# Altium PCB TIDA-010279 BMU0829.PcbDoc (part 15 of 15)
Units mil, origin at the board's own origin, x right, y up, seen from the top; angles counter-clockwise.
Board outline 11269.69 x 4438.98 mil, 4 copper layers (Top Layer, Signal Layer 1, Signal Layer 2, Bottom Layer), stack 61.6 mil thick; 1494 components, 725 nets, 3766 pads, 2728 vias.
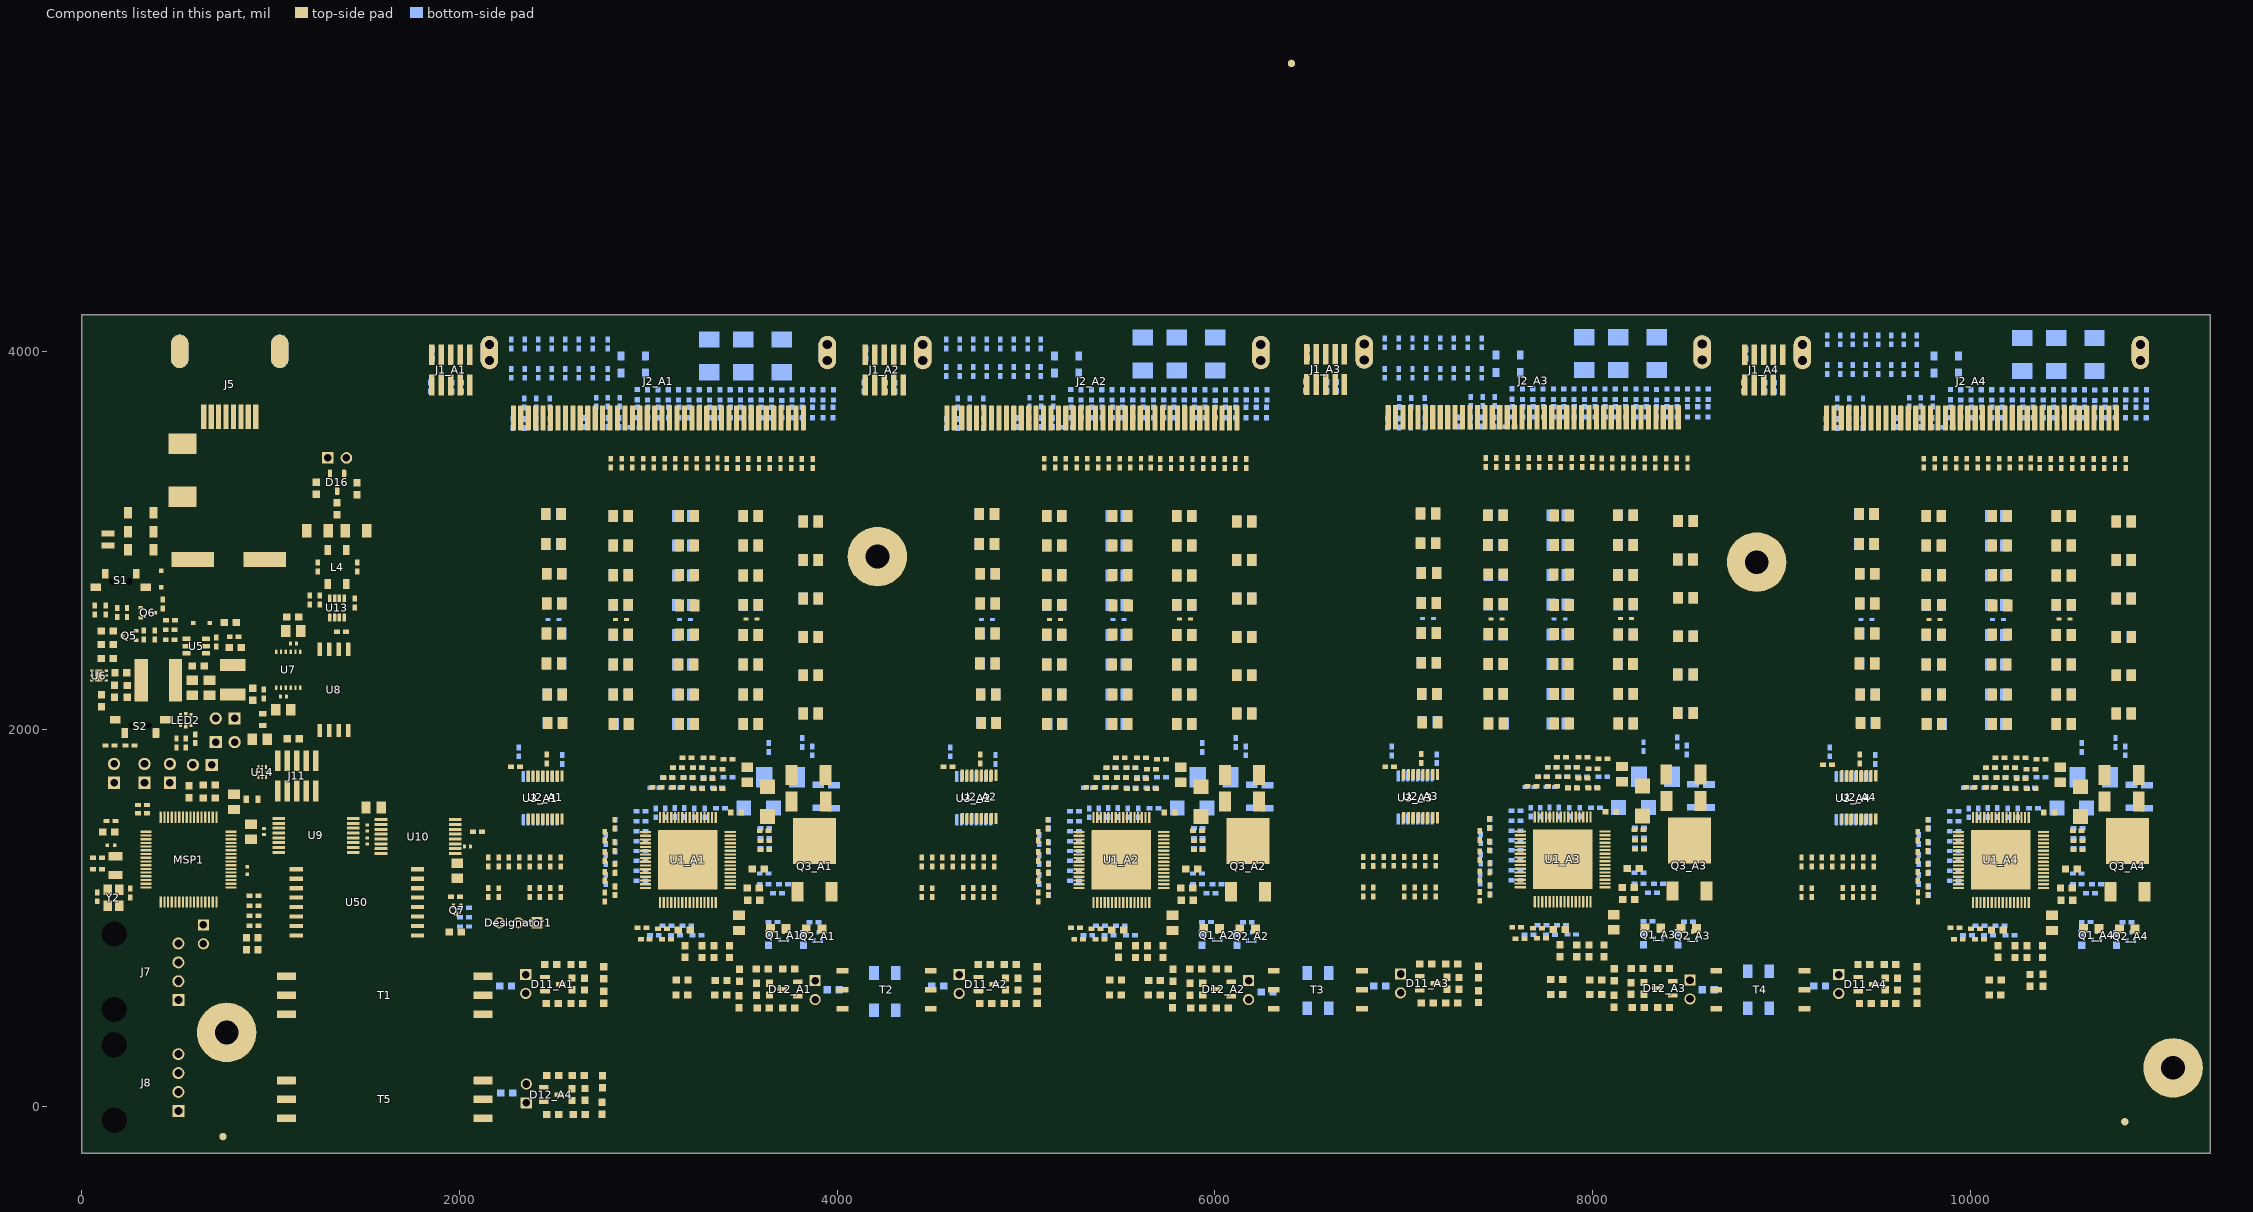
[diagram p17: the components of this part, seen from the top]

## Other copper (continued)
Bottom Layer:
  rectangle net DDGND: 1262.32,2387.93 1446.1,3280.04
  region net DDGND: 1272.87,2390.64 1272.87,2675.78 972.31,2675.78 972.31,2390.64
  pour cut-out: 1850.39,833.54 2280.32,833.54 2280.32,423.23 1850.39,423.23
  region net PGND: 1072.83,2234.25 1220.47,2234.25 1220.47,2155.51 1072.83,2155.51
  region net GND_Stage2: 1948.82,1574.8 2066.93,1574.8 2076.77,1564.96 2076.77,1427.17 2057.09,1407.48 1948.82,1407.48
  region net PGND: 875.98,1456.69 1023.62,1456.69 1023.62,1259.84 875.98,1259.84
  region net CELL0_A1: 2495.94,1980.81 2371.07,1980.81 2371.07,2251.95 2495.94,2251.95
  region net CB0_A1: 2638.57,1980.81 2510.32,1980.81 2510.32,2251.95 2638.57,2251.95
  region net CELL4_A1: 2721.94,2242.76 2846.81,2242.76 2846.81,1971.62 2721.94,1971.62
  region net CB4_A1: 2860.81,2242.76 2985.68,2242.76 2985.68,1971.62 2860.81,1971.62
  region net CELL8_A1: 3063.13,2242.76 3188.01,2242.76 3188.01,1971.62 3063.13,1971.62
  region net CB8_A1: 3200.11,2242.76 3324.99,2242.76 3324.99,1971.62 3200.11,1971.62
  region net CELL12_A1: 3417.1,2242.76 3541.98,2242.76 3541.98,1971.62 3417.1,1971.62
  region net CB12_A1: 3554.09,2242.76 3678.96,2242.76 3678.96,1971.62 3554.09,1971.62
  pour cut-out: 3933.27,791.2 4063.31,792.06 4063.31,419.92 4061.34,417.95 3933.27,417.95
  pour cut-out: 4145.41,833.54 4575.34,833.54 4575.34,423.23 4145.41,423.23
  region net ModuleP_L_A1: 3740.16,1604.33 4055.12,1604.33 4055.12,1250 3740.16,1250
  region net CELL16_A1: 3768.85,2361.15 3856.86,2361.15 3856.86,1979.4 3768.85,1979.4
  region net CB16_A1: 3867.28,2358.65 3955.3,2358.65 3955.3,1979.4 3867.28,1979.4
  region net CELL0_A2: 4790.96,1980.81 4666.08,1980.81 4666.08,2251.95 4790.96,2251.95
  region net CB0_A2: 4933.59,1980.81 4805.33,1980.81 4805.33,2251.95 4933.59,2251.95
  region net CELL4_A2: 5016.95,2242.76 5141.83,2242.76 5141.83,1971.62 5016.95,1971.62
  region net CB4_A2: 5155.82,2242.76 5280.7,2242.76 5280.7,1971.62 5155.82,1971.62
  region net CELL8_A2: 5358.15,2242.76 5483.02,2242.76 5483.02,1971.62 5358.15,1971.62
  region net CB8_A2: 5495.13,2242.76 5620.01,2242.76 5620.01,1971.62 5495.13,1971.62
  region net CELL1_A1: 2370.64,2560.13 2495.51,2560.13 2495.51,2288.99 2370.64,2288.99
  region net CB1_A1: 2509.88,2560.13 2636.22,2560.13 2636.22,2288.99 2509.88,2288.99
  region net CELL2_A1: 2370.64,2877.5 2495.51,2877.5 2495.51,2606.36 2370.64,2606.36
  region net CB2_A1: 2509.88,2877.5 2636.22,2877.5 2636.22,2606.36 2509.88,2606.36
  region net CELL5_A1: 2721.94,2560.13 2846.81,2560.13 2846.81,2288.99 2721.94,2288.99
  region net CB5_A1: 2860.81,2560.13 2985.68,2560.13 2985.68,2288.99 2860.81,2288.99
  region net CELL6_A1: 2721.94,2877.5 2846.81,2877.5 2846.81,2606.36 2721.94,2606.36
  region net CB6_A1: 2860.81,2877.5 2985.68,2877.5 2985.68,2606.36 2860.81,2606.36
  region net CELL3_A1: 2495.94,2927.18 2371.07,2927.18 2371.07,3198.32 2495.94,3198.32
  region net CB3_A1: 2638.57,2927.18 2510.32,2927.18 2510.32,3198.32 2638.57,3198.32
  region net CELL7_A1: 2721.94,3194.87 2846.81,3194.87 2846.81,2923.73 2721.94,2923.73
  region net CB7_A1: 2860.81,3194.87 2985.68,3194.87 2985.68,2923.73 2860.81,2923.73
  region net CELL9_A1: 3063.13,2560.13 3188.01,2560.13 3188.01,2288.99 3063.13,2288.99
  region net CB9_A1: 3200.11,2560.13 3324.99,2560.13 3324.99,2288.99 3200.11,2288.99
  region net CELL10_A1: 3063.13,2877.5 3188.01,2877.5 3188.01,2606.36 3063.13,2606.36
  pour cut-out: 4072.93,3779.53 4072.93,1197.01 3538.36,1197.01 3538.36,1491.73 3033.85,1491.73 3033.85,1134.49 2932.47,1136.13 2861.84,1065.51 2684.74,1065.51 2684.74,3336.63 2803.93,3336.63 2859.17,3391.88 2859.17,3508.39 2972.64,3508.39 3009.17,3544.92 3009.17,3779.53
  region net CELL13_A1: 3417.1,2560.13 3541.98,2560.13 3541.98,2288.99 3417.1,2288.99
  region net CB10_A1: 3200.11,2877.5 3324.99,2877.5 3324.99,2606.36 3200.11,2606.36
  region net CELL14_A1: 3417.1,2877.5 3541.98,2877.5 3541.98,2606.36 3417.1,2606.36
  region net CELL11_A1: 3072.49,3195.54 3188.01,3195.54 3188.01,2924.4 3072.49,2924.4
  region net CB11_A1: 3200.11,3194.87 3324.99,3194.87 3324.99,2923.73 3200.11,2923.73
  region net CELL15_A1: 3417.1,3195.54 3541.98,3195.54 3541.98,2924.4 3417.1,2924.4
  region net CELL17_A1: 3307.09,4055.12 3366.14,4055.12 3366.14,3986.22 3307.09,3986.22
  pour cut-out: 3097.29,4258.71 3097.29,3937.01 3896.33,3937.01 3896.33,4258.71
  region net CELL18_A1: 3494.09,4084.65 3543.31,4084.65 3553.15,4074.8 3553.15,3986.22 3494.09,3986.22
  region net CB13_A1: 3554.09,2560.13 3678.96,2560.13 3678.96,2288.99 3554.09,2288.99
  region net CB14_A1: 3554.09,2877.5 3678.96,2877.5 3678.96,2606.36 3554.09,2606.36
  region net CELL17_A1: 3768.53,2779.69 3856.54,2779.69 3856.54,2397.94 3768.53,2397.94
  region net CB17_A1: 3866.96,2777.19 3954.98,2777.19 3954.98,2397.94 3866.96,2397.94
  region net CELL1_A2: 4665.65,2560.13 4790.53,2560.13 4790.53,2288.99 4665.65,2288.99
  region net CB1_A2: 4804.9,2560.13 4931.23,2560.13 4931.23,2288.99 4804.9,2288.99
  region net CELL2_A2: 4665.65,2877.5 4790.53,2877.5 4790.53,2606.36 4665.65,2606.36
  region net CB2_A2: 4804.9,2877.5 4931.23,2877.5 4931.23,2606.36 4804.9,2606.36
  region net CB18_A1: 3866.1,3195.73 3954.11,3195.73 3954.11,2816.48 3866.1,2816.48
  region net CB15_A1: 3554.09,3194.87 3678.96,3194.87 3678.96,2923.73 3554.09,2923.73
  region net CELL18_A1: 3767.66,3198.23 3855.67,3198.23 3855.67,2816.48 3767.66,2816.48
  region net CELL3_A2: 4790.96,2927.18 4666.08,2927.18 4666.08,3198.32 4790.96,3198.32
  region net CB3_A2: 4933.59,2927.18 4805.33,2927.18 4805.33,3198.32 4933.59,3198.32
  region net CELL5_A2: 5016.95,2560.13 5141.83,2560.13 5141.83,2288.99 5016.95,2288.99
  region net CB5_A2: 5155.82,2560.13 5280.7,2560.13 5280.7,2288.99 5155.82,2288.99
  region net CELL6_A2: 5016.95,2877.5 5141.83,2877.5 5141.83,2606.36 5016.95,2606.36
  region net CB6_A2: 5155.82,2877.5 5280.7,2877.5 5280.7,2606.36 5155.82,2606.36
  region net CELL9_A2: 5358.15,2560.13 5483.02,2560.13 5483.02,2288.99 5358.15,2288.99
  region net CB9_A2: 5495.13,2560.13 5620.01,2560.13 5620.01,2288.99 5495.13,2288.99
  region net CELL10_A2: 5358.15,2877.5 5483.02,2877.5 5483.02,2606.36 5358.15,2606.36
  region net CB10_A2: 5495.13,2877.5 5620.01,2877.5 5620.01,2606.36 5495.13,2606.36
  region net CELL7_A2: 5016.95,3194.87 5141.83,3194.87 5141.83,2923.73 5016.95,2923.73
  region net CB7_A2: 5155.82,3194.87 5280.7,3194.87 5280.7,2923.73 5155.82,2923.73
  region net CELL11_A2: 5367.5,3195.54 5483.02,3195.54 5483.02,2924.4 5367.5,2924.4
  region net CB11_A2: 5495.13,3194.87 5620.01,3194.87 5620.01,2923.73 5495.13,2923.73
  region net ModuleP_A1: 3745.08,4055.12 3754.92,4045.28 3754.92,3996.06 3745.08,3986.22 3676.18,3986.22 3676.18,4055.12
  pour cut-out: 6228.28,791.2 6358.33,792.06 6358.33,419.92 6356.36,417.95 6228.28,417.95
  pour cut-out: 6482.01,836.75 6911.93,836.75 6911.93,426.44 6482.01,426.44
  region net ModuleP_L_A2: 6035.17,1604.33 6350.13,1604.33 6350.13,1250 6035.17,1250
  region net CELL12_A2: 5712.12,2242.76 5836.99,2242.76 5836.99,1971.62 5712.12,1971.62
  region net CB12_A2: 5849.1,2242.76 5973.98,2242.76 5973.98,1971.62 5849.1,1971.62
  region net CELL16_A2: 6063.86,2361.15 6151.88,2361.15 6151.88,1979.4 6063.86,1979.4
  region net CB16_A2: 6162.3,2358.65 6250.32,2358.65 6250.32,1979.4 6162.3,1979.4
  region net CB0_A3: 7270.19,1984.02 7141.93,1984.02 7141.93,2255.16 7270.19,2255.16
  region net CELL0_A3: 7127.56,1984.02 7002.68,1984.02 7002.68,2255.16 7127.56,2255.16
  pour cut-out: 6367.94,3779.53 6367.94,1197.01 5833.37,1197.01 5833.37,1491.73 5328.87,1491.73 5328.87,1134.49 5227.48,1136.13 5156.86,1065.51 4979.76,1065.51 4979.76,3336.63 5098.95,3336.63 5154.19,3391.88 5154.19,3508.39 5267.66,3508.39 5304.19,3544.92 5304.19,3779.53
  region net CELL13_A2: 5712.12,2560.13 5836.99,2560.13 5836.99,2288.99 5712.12,2288.99
  region net CB13_A2: 5849.1,2560.13 5973.98,2560.13 5973.98,2288.99 5849.1,2288.99
  region net CELL14_A2: 5712.12,2877.5 5836.99,2877.5 5836.99,2606.36 5712.12,2606.36
  region net CB14_A2: 5849.1,2877.5 5973.98,2877.5 5973.98,2606.36 5849.1,2606.36
  region net CB15_A2: 5849.1,3194.87 5973.98,3194.87 5973.98,2923.73 5849.1,2923.73
  region net CB17_A2: 6161.98,2777.19 6250,2777.19 6250,2397.94 6161.98,2397.94
  region net CELL17_A2: 6063.54,2779.69 6151.56,2779.69 6151.56,2397.94 6063.54,2397.94
  region net CELL1_A3: 7002.25,2563.34 7127.12,2563.34 7127.12,2292.2 7002.25,2292.2
  region net CB1_A3: 7141.5,2563.34 7267.83,2563.34 7267.83,2292.2 7141.5,2292.2
  region net CB18_A2: 6161.11,3195.73 6249.13,3195.73 6249.13,2816.48 6161.11,2816.48
  region net CELL18_A2: 6062.67,3198.23 6150.69,3198.23 6150.69,2816.48 6062.67,2816.48
  region net CELL2_A3: 7002.25,2880.71 7127.12,2880.71 7127.12,2609.57 7002.25,2609.57
  region net CB2_A3: 7141.5,2880.71 7267.83,2880.71 7267.83,2609.57 7141.5,2609.57
  region net CELL4_A3: 7353.55,2245.97 7478.42,2245.97 7478.42,1974.83 7353.55,1974.83
  region net CB4_A3: 7492.42,2245.97 7617.3,2245.97 7617.3,1974.83 7492.42,1974.83
  region net CELL8_A3: 7694.74,2245.97 7819.62,2245.97 7819.62,1974.83 7694.74,1974.83
  region net CB8_A3: 7831.73,2245.97 7956.6,2245.97 7956.6,1974.83 7831.73,1974.83
  region net CELL12_A3: 8048.72,2245.97 8173.59,2245.97 8173.59,1974.83 8048.72,1974.83
  region net CB12_A3: 8185.7,2245.97 8310.57,2245.97 8310.57,1974.83 8185.7,1974.83
  region net CELL5_A3: 7353.55,2563.34 7478.42,2563.34 7478.42,2292.2 7353.55,2292.2
  region net CB5_A3: 7492.42,2563.34 7617.3,2563.34 7617.3,2292.2 7492.42,2292.2
  region net CELL6_A3: 7353.55,2880.71 7478.42,2880.71 7478.42,2609.57 7353.55,2609.57
  region net CB6_A3: 7492.42,2880.71 7617.3,2880.71 7617.3,2609.57 7492.42,2609.57
  region net CELL9_A3: 7694.74,2563.34 7819.62,2563.34 7819.62,2292.2 7694.74,2292.2
  region net CB9_A3: 7831.73,2563.34 7956.6,2563.34 7956.6,2292.2 7831.73,2292.2
  pour cut-out: 8704.54,3783.53 8704.54,1200.22 8169.97,1200.22 8169.97,1494.94 7665.47,1494.94 7665.47,1137.7 7564.08,1139.34 7493.46,1068.71 7316.36,1068.71 7316.36,3339.84 7435.54,3339.84 7490.79,3395.09 7490.79,3511.6 7604.25,3511.6 7640.79,3548.13 7640.79,3783.53
  region net CELL13_A3: 8048.72,2563.34 8173.59,2563.34 8173.59,2292.2 8048.72,2292.2
  region net CB13_A3: 8185.7,2563.34 8310.57,2563.34 8310.57,2292.2 8185.7,2292.2
  region net CELL10_A3: 7694.74,2880.71 7819.62,2880.71 7819.62,2609.57 7694.74,2609.57
  region net CB10_A3: 7831.73,2880.71 7956.6,2880.71 7956.6,2609.57 7831.73,2609.57
  region net CELL14_A3: 8048.72,2880.71 8173.59,2880.71 8173.59,2609.57 8048.72,2609.57
  region net CB14_A3: 8185.7,2880.71 8310.57,2880.71 8310.57,2609.57 8185.7,2609.57
  pour cut-out: 8564.88,794.41 8694.92,795.27 8694.92,423.13 8692.95,421.16 8564.88,421.16
  pour cut-out: 8802.24,833.54 9232.16,833.54 9232.16,423.23 8802.24,423.23
  region net ModuleP_L_A3: 8371.77,1607.54 8686.73,1607.54 8686.73,1253.21 8371.77,1253.21
  pour cut-out: 10885.11,791.2 11015.15,792.06 11015.15,419.92 11013.18,417.95 10885.11,417.95
  region net ModuleP_L_A4: 10692,1604.33 11006.96,1604.33 11006.96,1250 10692,1250
  region net CELL16_A3: 8400.46,2364.35 8488.48,2364.35 8488.48,1982.6 8400.46,1982.6
  region net CB16_A3: 8498.9,2361.85 8586.91,2361.85 8586.91,1982.6 8498.9,1982.6
  region net CB0_A4: 9590.41,1980.81 9462.16,1980.81 9462.16,2251.95 9590.41,2251.95
  region net CELL0_A4: 9447.79,1980.81 9322.91,1980.81 9322.91,2251.95 9447.79,2251.95
  region net CELL4_A4: 9673.78,2242.76 9798.65,2242.76 9798.65,1971.62 9673.78,1971.62
  region net CB4_A4: 9812.65,2242.76 9937.53,2242.76 9937.53,1971.62 9812.65,1971.62
  region net CELL17_A3: 8400.14,2782.9 8488.16,2782.9 8488.16,2401.15 8400.14,2401.15
  region net CELL1_A4: 9322.48,2560.13 9447.35,2560.13 9447.35,2288.99 9322.48,2288.99
  region net CB17_A3: 8498.58,2780.4 8586.59,2780.4 8586.59,2401.15 8498.58,2401.15
  region net CELL18_A3: 8399.27,3201.44 8487.29,3201.44 8487.29,2819.69 8399.27,2819.69
  region net CELL2_A4: 9322.48,2877.5 9447.35,2877.5 9447.35,2606.36 9322.48,2606.36
  region net CB18_A3: 8497.71,3198.94 8585.72,3198.94 8585.72,2819.69 8497.71,2819.69
  region net CB1_A4: 9461.73,2560.13 9588.06,2560.13 9588.06,2288.99 9461.73,2288.99
  region net CB5_A4: 9812.65,2560.13 9937.53,2560.13 9937.53,2288.99 9812.65,2288.99
  region net CELL5_A4: 9673.78,2560.13 9798.65,2560.13 9798.65,2288.99 9673.78,2288.99
  region net CB2_A4: 9461.73,2877.5 9588.06,2877.5 9588.06,2606.36 9461.73,2606.36
  region net CB6_A4: 9812.65,2877.5 9937.53,2877.5 9937.53,2606.36 9812.65,2606.36
  region net CELL6_A4: 9673.78,2877.5 9798.65,2877.5 9798.65,2606.36 9673.78,2606.36
  region net CELL8_A4: 10014.97,2242.76 10139.85,2242.76 10139.85,1971.62 10014.97,1971.62
  region net CB8_A4: 10151.96,2242.76 10276.83,2242.76 10276.83,1971.62 10151.96,1971.62
  region net CB12_A4: 10505.93,2242.76 10630.8,2242.76 10630.8,1971.62 10505.93,1971.62
  region net CELL12_A4: 10368.95,2242.76 10493.82,2242.76 10493.82,1971.62 10368.95,1971.62
  region net CB16_A4: 10819.13,2358.65 10907.14,2358.65 10907.14,1979.4 10819.13,1979.4
  region net CELL16_A4: 10720.69,2361.15 10808.71,2361.15 10808.71,1979.4 10720.69,1979.4
  region net CELL9_A4: 10014.97,2560.13 10139.85,2560.13 10139.85,2288.99 10014.97,2288.99
  pour cut-out: 11024.77,3779.53 11024.77,1197.01 10490.2,1197.01 10490.2,1491.73 9985.7,1491.73 9985.7,1134.49 9884.31,1136.13 9813.69,1065.51 9636.59,1065.51 9636.59,3336.63 9755.77,3336.63 9811.02,3391.88 9811.02,3508.39 9924.48,3508.39 9961.02,3544.92 9961.02,3779.53
  region net CB9_A4: 10151.96,2560.13 10276.83,2560.13 10276.83,2288.99 10151.96,2288.99
  region net CELL10_A4: 10014.97,2877.5 10139.85,2877.5 10139.85,2606.36 10014.97,2606.36
  region net CB10_A4: 10151.96,2877.5 10276.83,2877.5 10276.83,2606.36 10151.96,2606.36
  region net CB11_A4: 10151.96,3194.87 10276.83,3194.87 10276.83,2923.73 10151.96,2923.73
  region net CELL13_A4: 10368.95,2560.13 10493.82,2560.13 10493.82,2288.99 10368.95,2288.99
  region net CB13_A4: 10505.93,2560.13 10630.8,2560.13 10630.8,2288.99 10505.93,2288.99
  region net CB17_A4: 10818.81,2777.19 10906.82,2777.19 10906.82,2397.94 10818.81,2397.94
  region net CELL17_A4: 10720.37,2779.69 10808.39,2779.69 10808.39,2397.94 10720.37,2397.94
  region net CELL14_A4: 10368.95,2877.5 10493.82,2877.5 10493.82,2606.36 10368.95,2606.36
  region net CB14_A4: 10505.93,2877.5 10630.8,2877.5 10630.8,2606.36 10505.93,2606.36
  region net CB15_A4: 10505.93,3194.87 10630.8,3194.87 10630.8,2923.73 10505.93,2923.73
  region net CB18_A4: 10817.94,3195.73 10905.95,3195.73 10905.95,2816.48 10817.94,2816.48
  region net CELL18_A4: 10719.5,3198.23 10807.52,3198.23 10807.52,2816.48 10719.5,2816.48
  region net CELL15_A2: 5712.12,3195.54 5836.99,3195.54 5836.99,2924.4 5712.12,2924.4
  region net CELL3_A3: 7127.56,2930.39 7002.68,2930.39 7002.68,3201.53 7127.56,3201.53
  region net CB3_A3: 7270.19,2930.39 7141.93,2930.39 7141.93,3201.53 7270.19,3201.53
  region net CELL7_A3: 7353.55,3198.08 7478.42,3198.08 7478.42,2926.93 7353.55,2926.93
  region net CB7_A3: 7492.42,3198.08 7617.3,3198.08 7617.3,2926.93 7492.42,2926.93
  region net CELL11_A3: 7704.1,3198.75 7819.62,3198.75 7819.62,2927.61 7704.1,2927.61
  region net CB11_A3: 7831.73,3198.08 7956.6,3198.08 7956.6,2926.93 7831.73,2926.93
  region net CELL15_A3: 8048.72,3198.75 8173.59,3198.75 8173.59,2927.61 8048.72,2927.61
  region net CB15_A3: 8185.7,3198.08 8310.57,3198.08 8310.57,2926.93 8185.7,2926.93
  region net CELL17_A2: 5600.39,4064.96 5659.45,4064.96 5659.45,3996.06 5600.39,3996.06
  pour cut-out: 5392.31,4258.71 5392.31,3937.01 6191.35,3937.01 6191.35,4258.71
  region net CELL18_A2: 5777.56,4094.49 5826.77,4094.49 5836.61,4084.65 5836.61,3996.06 5777.56,3996.06
  region net ModuleP_A2: 6028.54,4064.96 6038.39,4055.12 6038.39,4005.91 6028.54,3996.06 5959.65,3996.06 5959.65,4064.96
  region net CELL17_A3: 7933.07,4074.8 7992.13,4074.8 7992.13,4005.91 7933.07,4005.91
  pour cut-out: 7728.9,4261.92 7728.9,3946.85 8527.94,3946.85 8527.94,4261.92
  region net CELL18_A3: 8100.39,4099.41 8149.61,4099.41 8159.45,4089.57 8159.45,4000.98 8100.39,4000.98
  region net CELL3_A4: 9447.79,2927.18 9322.91,2927.18 9322.91,3198.32 9447.79,3198.32
  region net CB3_A4: 9590.41,2927.18 9462.16,2927.18 9462.16,3198.32 9590.41,3198.32
  region net CELL7_A4: 9673.78,3194.87 9798.65,3194.87 9798.65,2923.73 9673.78,2923.73
  region net CB7_A4: 9812.65,3194.87 9937.53,3194.87 9937.53,2923.73 9812.65,2923.73
  region net CELL11_A4: 10024.33,3195.54 10139.85,3195.54 10139.85,2924.4 10024.33,2924.4
  region net CELL15_A4: 10368.95,3195.54 10493.82,3195.54 10493.82,2924.4 10368.95,2924.4
  region net ModuleP_A3: 8366.14,4060.04 8375.98,4050.2 8375.98,4000.98 8366.14,3991.14 8297.24,3991.14 8297.24,4060.04
  region net CELL17_A4: 10255.91,4060.04 10314.96,4060.04 10314.96,3991.14 10255.91,3991.14
  pour cut-out: 10049.13,4258.71 10049.13,3937.01 10848.17,3937.01 10848.17,4258.71
  region net CELL18_A4: 10433.07,4104.33 10482.28,4104.33 10492.13,4094.49 10492.13,4005.91 10433.07,4005.91
  region net ModuleP_A4: 10693.9,4064.96 10703.74,4055.12 10703.74,4005.91 10693.9,3996.06 10625,3996.06 10625,4064.96
  text ".Layer_Name" at 577,-858.49 h60
Multi-Layer:
  pour cut-out: 2086.61,3403 2086.61,1564.96 1486.22,1564.96 1486.22,3409.13
  pour cut-out: 1505.91,915.35 2066.93,915.35 2086.61,895.67 2086.61,-246.06 1515.75,-246.06 1505.91,-236.22
  pour cut-out: 1781.5,4201.15 1781.5,3415.35 1496.06,3415.35 1496.06,4204.06

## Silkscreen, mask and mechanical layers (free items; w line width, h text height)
Top Overlay:
  text "'.PRJ_Number'.PCB_Rev" at 1692.91,1781.5 h108.27 r90
  text ".Layer_Name" at 577,-858.49 h60
Bottom Overlay:
  text ".Layer_Name" at 577,-858.49 h60
Top Paste:
  text ".Layer_Name" at 577,-858.49 h60
Bottom Paste:
  text ".Layer_Name" at 577,-858.49 h60
Top Solder:
  text ".Layer_Name" at 577,-858.49 h60
  text ".Layer_Name" at 577,-858.49 h60
Bottom Solder:
  text ".Layer_Name" at 577,-858.49 h60
Drill Guide:
  text ".Layer_Name" at 577,-858.49 h60
M1 Board Outline:
  the board outline again, w10
  text ".Layer_Name" at 577,-858.49 h60
M2 Board Dimensions:
  rectangle: 0,-275 125,-150
  rectangle: 125,-400 500,-275
  lines w7: 0,-275 1000,-275 ; 125,-400 125,-150 ; 250,-400 250,-150 ; 500,-400 500,-150 ; 750,-400 750,-150 ; 0,-150 1000,-150 ; 0,-150 1000,-150 ; 0,-150 0,-400 1000,-400 1000,-150
  text ".Layer_Name" at 577,-858.49 h60
M3 3D STEP Top:
  text ".Layer_Name" at 577,-858.49 h60
M4 3D STEP Bottom:
  text ".Layer_Name" at 577,-858.49 h60
M5 Assembly Top:
  lines w10: -292,-930.17 6308,-930.17 ; -292,-726.83 6310,-726.83 ; -292,-523.5 -292,-1133.5 3713,-1133.5 6310,-1133.5 ; 1284,-1133.5 -291.5,-1133.5 -291.5,-523.5 6310,-523.5 ; 2173,-1133.5 2173,-523.5 ; 3440,-726.83 3440,-523.5 ; 4280,-726.83 4280,-523.5 ; 4902,-1140 4902,-937.17 ; 5268.4,2575.7 5268.4,3185.7
  text "COMPONENTS MARKED 'DNP' SHOULD NOT BE POPULATED." at 1153.5,-318.5 h60
  text "ASSEMBLY VARIANT:" at 1153,-434 h60
  text ".VariantName" at 2189,-434 h60
  text "PCB VIEWED FROM TOP SIDE" at -228.5,-655.67 h60
  text "BOARD #:" at 2248,-655.67 h60
  text ".PRJ_Number" at 2793.5,-655.67 h60
  text "REV:" at 3638,-655.67 h60
  text ".PCB_Rev" at 3929.5,-655.67 h60
  text "SVN REV:" at 4476,-655.67 h60
  text ".VersionControl_RevNumber" at 4982,-655.67 h60
  text "TID #:" at 2248,-859 h60
  text ".TID" at 2793.5,-859 h60
  text "PLOT NAME =" at -228.5,-1064.34 h60
  text ".plot_File_Name" at 577,-1064.34 h60
  text "GENERATED    :" at 2250,-1064.34 h60
  text ".Print_Date" at 3119.5,-1064.34 h60
  text ".Print_Time" at 3848.5,-1064.34 h60
  text "TEXAS INSTRUMENTS" at 5113,-1064.34 h60
M6 Assembly Bottom:
  lines w10: -292.5,-727.33 6309.5,-727.33 ; -290.5,-930.67 6309.5,-930.67 ; 1115.5,-1140.5 1115.5,-937.67 ; 1737.5,-727.33 1737.5,-524 ; 2577.5,-727.33 2577.5,-524 ; 3844.5,-1134 3844.5,-524 ; 4733.5,-1134 6309,-1134 ; 5267.4,2575.2 5267.4,3185.2 ; 5267.9,2575.2 5267.9,3185.2 ; 6309,-524 -292.5,-524 -292.5,-1134 2304.5,-1134 6309.5,-1134
  text "ASSEMBLY VARIANT:" at 5055.4,3275.2 h60
  text "PLOT NAME =" at 5204.4,2644.36 h60
  text "COMPONENTS MARKED 'DNP' SHOULD NOT BE POPULATED." at 6102,-318 h60
  text ".VariantName" at 5058,-434 h60
  text ".VersionControl_RevNumber" at 1035.5,-656.17 h60
  text "SVN REV:" at 1541.5,-656.17 h60
  text ".PCB_Rev" at 2088,-656.17 h60
  text "REV:" at 2379.5,-656.17 h60
  text ".PRJ_Number" at 3224,-656.17 h60
  text "BOARD #:" at 3769.5,-656.17 h60
  text "PCB VIEWED FROM BOTTOM SIDE" at 6246,-656.17 h60
  text ".TID" at 3224,-859.5 h60
  text "TID #:" at 3769.5,-859.5 h60
  text "TEXAS INSTRUMENTS" at 904.5,-1064.84 h60
  text ".Print_Time" at 2169,-1064.84 h60
  text ".Print_Date" at 2898,-1064.84 h60
  text "GENERATED    :" at 3767.5,-1064.84 h60
  text ".plot_File_Name" at 5440.5,-1064.84 h60
M9 Title Sheet:
  drawing of 57 lines, arcs and shapes, not listed
  text "1" at 739.84,8036.5 h70
  text "2" at 3235.5,8036.5 h70
  text "3" at 5724.84,8036.5 h70
  text "4" at 8231.51,8036.5 h70
  text "5" at 10730.5,8036.5 h70
  text "6" at 13235.5,8036.5 h70
  text "A" at -416.5,6893.5 h70
  text "A" at 14383.5,6893.5 h70
  text "B" at -416.5,4513.5 h70
  text "B" at 14383.5,4513.5 h70
  text "3" at 4683.25,2170.11 h70
  text "C" at -416.5,2138.5 h70
  text "C" at 14383.5,2138.5 h70
  text "PROJECT TITLE:" at 11343.5,277.5 h45
  text ".PRJ_Title" at 11393.5,144.17 h70
  text "DESIGNED FOR:" at 11343.5,-23.5 h45
  text ".PRJ_Customer" at 11393.5,-163.5 h70
  text "D" at -416.5,-231.5 h70
  text "D" at 14383.5,-231.5 h70
  text "FILE NAME:" at 11343.5,-323.5 h45
  text ".PCB_File_Name_No_Path" at 11393.5,-443.5 h70
  text "Texas Instruments (TI) and/or its licensors do not warrant the accuracy or completeness of this specification" at 6374,-605.34 h45
  text "ENGINEER:" at 11343.5,-613.5 h45
  text "LAYOUT BY:" at 12848.5,-613.5 h45
  text "or any information contained therein. TI and/or its licensors do not warrant that this design will meet" at 6329.01,-718 h45
  text ".PRJ_Engineer" at 11393.5,-768.49 h70
  text ".PCB_Layout" at 12899,-768.49 h70
  text "the specifications, will be suitable for your application or fit for any particular purpose, or will operate in" at 6329.01,-830.67 h45
  text ".Layer_Name" at 577,-858.49 h60
  text "ALTIUM DESIGNER VERSION:" at 12848.5,-923.5 h45
  text "an implementation. TI and/or its licensors do not warrant that the design is production worthy. You should" at 6329.01,-943.33 h45
  text "completely validate and test your design implementation to confirm the system functionality for your application." at 6374,-1056 h45
  text ".print_Scale" at 11393.5,-1056.83 h70
  text ".Application_BuildNumber" at 12899,-1056.83 h70
  text "1" at 739.84,-1263.5 h70
  text "2" at 3235.5,-1263.5 h70
  text "4" at 8231.51,-1263.5 h70
  text "5" at 10730.5,-1263.5 h70
  text "6" at 13235.5,-1263.5 h70
M10 Fab Notes:
  drawing of 189 lines, arcs and shapes, not listed
  text "DESIGN INFORMATION" at 12382.02,6356.17 h60
  text "MIN. TRACK WIDTH:" at 11737.46,6224.05 h60
  text "8" at 12833.7,6224.05 h60
  text "MIL" at 12988.46,6224.05 h60
  text "7.874" at 12667.32,6102.36 h60
  text "MIN. CLEARANCE:" at 11737.46,6099.92 h60
  text "MIL" at 12988.46,6099.92 h60
  text "MIN. VIA PAD SIZE:" at 11737.46,5975.8 h60
  text "24" at 12803.71,5975.8 h60
  text "MIL" at 12988.46,5975.8 h60
  text "0.05mm (2MIL)" at 12432.46,5845.9 h60
  text "MINIMUM ANNULAR RING" at 11408.23,5837.67 h60
  text "EXTERNAL" at 13140.46,5837.67 h60
  text "PER" at 11608.23,5727.55 h60
  text "IPC-D-275 CLASS 2 LEVEL C" at 11828.23,5727.54 h60
  text "MIL, HOLES" at 13316.46,5627.07 h60
  text "+/-" at 12924,5618.48 h60
  text "+/-" at 13778,5618.48 h60
  text "REGISTRATION TOLERANCES:" at 11408.23,5617.42 h60
  text "METAL" at 12608,5617.42 h60
  text "5" at 13184.2,5617.42 h60
  text "3" at 14017.2,5617.42 h60
  text "MIL" at 14133.46,5617.42 h60
  text "HOLE SIZE TOLERANCE (UNLESS OTHERWISE SPECIFIED):" at 11408.23,5519.1 h60
  text "+/-" at 13778,5516.23 h60
  text "3" at 14017.2,5515.17 h60
  text "MIL" at 14133.46,5515.17 h60
  text "MATERIAL:" at 11333.46,5377.52 h60
  text "FR-4 High Tg" at 12319.9,5249 h60
  text "X" at 12175.46,5241.01 h60
  text "FR-4" at 11754.46,5236.49 h60
  text "OTHER" at 13242.46,5236.49 h60
  text "62 MIL (1.6mm) +/-10%" at 12074.56,5093.46 h60
  text "X" at 11954.46,5091.01 h60
  text "THICKNESS:" at 11408.23,5085.24 h60
  text "OTHER" at 13359.46,5085.24 h60
  text "TOLERANCE:" at 11408.23,4946.92 h60
  text "X" at 12256.46,4946.92 h60
  text "ANSI IPC-6012 TYPE 3 CLASS 2" at 12434.48,4946.92 h60
  text "OTHER +/-" at 12434.46,4802.73 h60
  text "BOW & TWIST:" at 11408.23,4657.54 h60
  text "X" at 12256.46,4657.54 h60
  text "ANSI IPC-6012 TYPE 3 CLASS 2" at 12434.48,4657.54 h60
  text "OTHER +/-" at 12434.46,4510.85 h60
  text "DRILLING:" at 11333.46,4380.23 h60
  text "NC_DRILL FILES" at 13094.46,4275.04 h60
  text "REFERENCE:" at 11408.23,4271.1 h60
  text "X" at 12065.46,4271.01 h60
  text "AS SHOWN" at 12243.46,4271.1 h60
  text "X" at 12966.46,4271.1 h60
  text "OTHER" at 13392.46,4128.85 h60
  text "PTH COPPER THICKNESS:" at 11407.91,4125.32 h60
  text "X" at 12547.14,4125.32 h60
  text "20-30 um" at 12675.14,4125.32 h60
  text "BOARD FINISH:" at 11333.46,3977.73 h60
  text "SILKSCREEN:" at 11488.68,3867.6 h60
  text "X" at 12446.46,3867.6 h60
  text "TOP" at 12563.46,3867.6 h60
  text "X" at 12956.46,3867.6 h60
  text "BOTTOM" at 13074.46,3867.6 h60
  text "SILKSCREEN COLOR:" at 11488.68,3712.41 h60
  text "X" at 12445.46,3712.41 h60
  text "WHITE" at 12563.46,3712.41 h60
  text "OTHER" at 13074.46,3712.41 h60
  text "X" at 12576.46,3568.96 h60
  text "GREEN" at 12694.46,3568.96 h60
  text "OTHER" at 13312.46,3568.96 h60
  text "SOLDER RESIST COLOR:" at 11488.68,3562.1 h60
  text "X" at 12576.46,3414.71 h60
  text "MATTE" at 12694.46,3414.71 h60
  text "SEMI-GLOSS" at 13312,3414.07 h60
  text "IMMERSION GOLD (ENIG)" at 12394.46,3241.94 h60
  text "ENEPIG" at 13732,3234.72 h60
  text "SURFACE FINISH:" at 11333.46,3233.72 h60
  text "X" at 12216.46,3233.72 h60
  text "IMM. TIN/SILVER OR EQUIV" at 11663,3096.4 h60
  text "OTHER" at 13094.46,3092.47 h60
  text "ARRAY/PANEL:" at 11333.46,2937.09 h60
  text "CUT AND TRIM PER M1 BOARD OUTLINE" at 12394.46,2928.87 h60
  text "N.C. ROUTE" at 12394.46,2792.9 h60
  text "X" at 13082.46,2792.9 h60
  text "V. SCORE" at 13260.46,2792.9 h60
  text "CERTIFICATION:" at 11333.46,2663.77 h60
  text "MATERIALS AND WORKMANSHIP FOR ALL PCBS" at 12058.46,2663.77 h60
  text "TO MEET OR EXCEED THE REQUIREMENTS OF:" at 12058.46,2569.71 h60
  text "X" at 11695.97,2441.08 h60
  text "ANSI IPC-A-600F CLASS ->" at 11823.96,2441.08 h60
  text "X" at 13471.97,2441.08 h60
  text "2" at 13581.96,2441.08 h60
  text "1" at 13266.96,2439.58 h60
  text "3" at 13935.96,2439.58 h60
  text "X" at 12507.97,2293.39 h60
  text "RoHS" at 12635.96,2293.39 h60
  text "OTHER" at 13280.36,2293.39 h60
  text "PER ORDER" at 13677.42,2293.39 h60
  text "ALL BOARDS MUST MEET OR EXCEED UL94-V0 REQUIREMENTS." at 11361,2139.57 h60
  text "PCB MUST BEAR THE UL94V-0 UL REGISTERED MATERIAL ID NUMBER" at 11361,2023.5 h60
  text "ADDITIONAL REQUIREMENTS:" at 11333.46,1854.08 h60
  text "MICROSECTION:" at 11408.23,1746.95 h60
  text "YES" at 12313.96,1746.95 h60
  text "REQUIRED" at 13175.46,1602.62 h60
  text "BARE BOARD ELEC. TEST:" at 11408.23,1599.76 h60
  text "NONE" at 12713.96,1599.76 h60
  text "X" at 13057.46,1599.76 h60
  text "PER ORDER" at 13767.46,1599.76 h60
  text "XX MIL VIAS REQUIRE NON-CONDUCTIVE FILL AND PLANARIZE" at 11576.38,1394.82 h59
  text "XX MIL VIAS REQUIRE CONDUCTIVE FILL AND PLANARIZE" at 11584.38,1290.84 h60
  text "OUTER XX MIL TRACES REQUIRE 50 OHM SINGLE-ENDED IMPEDANCE" at 11583.39,1127.46 h58
  text "LAYER 2 & 3 (INNER LAYERS) XX MIL WIDE, XX MIL SPACE / TRACES REQUIRE 100 OHM DIFFERENTIAL IMPEDANCE" at 11575.39,891.74 h60
  text ".Layer_Name" at 577,-858.49 h60
M11 Gerber Information:
  lines w10: -292,-930.17 6308,-930.17 ; -292,-726.83 6310,-726.83 ; -292,-523.5 -292,-1133.5 3713,-1133.5 6310,-1133.5 ; 1284,-1133.5 -291.5,-1133.5 -291.5,-523.5 6310,-523.5 ; 2173,-1133.5 2173,-523.5 ; 3440,-726.83 3440,-523.5 ; 4280,-726.83 4280,-523.5 ; 4902,-1140 4902,-937.17 ; 5268.4,2575.7 5268.4,3185.7
  text "ALL ARTWORK VIEWED FROM TOP SIDE" at -228.5,-655.67 h60
  text "BOARD #:" at 2248,-655.67 h60
  text ".PRJ_Number" at 2793.5,-655.67 h60
  text "REV:" at 3638,-655.67 h60
  text ".PCB_Rev" at 3929.5,-655.67 h60
  text "SVN REV:" at 4476,-655.67 h60
  text ".VersionControl_RevNumber" at 4982,-655.67 h60
  text "LAYER NAME =" at -228.5,-858.49 h60
  text "TID #:" at 2248,-859 h60
  text ".TID" at 2793.5,-859 h60
  text "PLOT NAME =" at -228.5,-1064.34 h60
  text ".plot_File_Name" at 577,-1064.34 h60
  text "GENERATED    :" at 2250,-1064.34 h60
  text ".Print_Date" at 3119.5,-1064.34 h60
  text ".Print_Time" at 3848.5,-1064.34 h60
  text "TEXAS INSTRUMENTS" at 5113,-1064.34 h60
M12 Stackup:
  drawing of 295 lines, arcs and shapes, not listed
  text "Layer" at 9821.59,7874.94 h60
  text "Name" at 10231.51,7874.94 h60
  text "Material" at 11171.25,7874.94 h60
  text "Thickness" at 12031.02,7874.94 h60
  text "Constant" at 12680.85,7874.94 h60
  text "Board Layer Stack" at 13250.71,7874.94 h60
  text "Top Overlay" at 10231.51,7754.94 h60
  text "Top Solder" at 10231.51,7634.94 h60
  text "Solder Resist" at 11171.25,7634.94 h60
  text "0.40mil" at 12031.02,7634.94 h60
  text "3.5" at 12680.85,7634.94 h60
  text "1" at 9821.59,7514.94 h60
  text "Top Layer" at 10231.51,7514.94 h60
  text "2.80mil" at 12031.02,7514.94 h60
  text "Dielectric 1" at 10231.51,7394.94 h60
  text "FR-4 High Tg" at 11171.25,7394.94 h60
  text "8.00mil" at 12031.02,7394.94 h60
  text "4.2" at 12680.85,7394.94 h60
  text "2" at 9821.59,7274.94 h60
  text "Signal Layer 1" at 10231.51,7274.94 h60
  text "1.40mil" at 12031.02,7274.94 h60
  text "Dielectric 2" at 10231.51,7154.94 h60
  text "FR-4 High Tg" at 11171.25,7154.94 h60
  text "37.20mil" at 12031.02,7154.94 h60
  text "4.2" at 12680.85,7154.94 h60
  text "3" at 9821.59,7034.94 h60
  text "Signal Layer 2" at 10231.51,7034.94 h60
  text "1.40mil" at 12031.02,7034.94 h60
  text "Dielectric 3" at 10231.51,6914.94 h60
  text "FR-4 High Tg" at 11171.25,6914.94 h60
  text "8.00mil" at 12031.02,6914.94 h60
  text "4.2" at 12680.85,6914.94 h60
  text "4" at 9821.59,6794.94 h60
  text "Bottom Layer" at 10231.51,6794.94 h60
  text "2.80mil" at 12031.02,6794.94 h60
  text "Bottom Solder" at 10231.51,6674.94 h60
  text "Solder Resist" at 11171.25,6674.94 h60
  text "0.40mil" at 12031.02,6674.94 h60
  text "3.5" at 12680.85,6674.94 h60
  text "Bottom Overlay" at 10231.51,6554.94 h60
  text ".Layer_Name" at 577,-858.49 h60
M13 Component Bodies Top:
  text ".Layer_Name" at 577,-858.49 h60
M14 Component Bodies Bottom:
  text ".Layer_Name" at 577,-858.49 h60
M15 Courtyards Top:
  text ".Layer_Name" at 577,-858.49 h60
M16 Courtyards Bottom:
  text ".Layer_Name" at 577,-858.49 h60
Drill Drawing:
  circle w10: c6397.05,6392.89 r16.56
  circle w10: c6397.05,6392.89 r27.59
  circle w10: c6397.05,5772.01 r27.59
  lines w10: 6369.45,5896.19 6397.05,5868.59 6424.64,5896.19 6397.05,5923.78 6369.45,5896.19 ; 6369.45,5992.77 6424.64,5992.77 6424.64,6047.96 6369.45,6047.96 6369.45,5992.77 ; 6369.45,6116.95 6397.05,6130.74 6424.64,6116.95 6410.84,6144.54 6424.64,6172.14 6397.05,6158.34 6369.45,6172.14 6383.25,6144.54 6369.45,6116.95 ; 6369.45,6254.92 6383.25,6254.92 6397.05,6241.12 6410.84,6254.92 6424.64,6254.92 6410.84,6268.72 6424.64,6282.51 6410.84,6282.51 6397.05,6296.31 6383.25,6282.51 6369.45,6282.51 6383.25,6268.72 6369.45,6254.92 ; 6369.45,6489.47 6369.45,6503.27 6383.25,6517.07 6369.45,6530.87 6369.45,6544.66 6383.25,6544.66 6397.05,6530.87 6410.84,6544.66 6424.64,6544.66 6424.64,6530.87 6410.84,6517.07 6424.64,6503.27 6424.64,6489.47 6410.84,6489.47 6397.05,6503.27 6383.25,6489.47 6369.45,6489.47 ; 6369.45,6668.84 6424.64,6668.84 6397.05,6613.65 6369.45,6668.84 ; 6369.45,6751.62 6383.25,6751.62 6383.25,6737.83 6410.84,6737.83 6410.84,6751.62 6424.64,6751.62 6424.64,6779.22 6410.84,6779.22 6410.84,6793.02 6383.25,6793.02 6383.25,6779.22 6369.45,6779.22 6369.45,6751.62
  lines w12: 6319.42,5707.17 9549.94,5707.17 ; 6319.42,6824.75 9549.94,6824.75 ; 6657.28,5582.99 6657.28,6948.93 ; 6989.28,5582.99 6989.28,6948.93 ; 7625.84,5582.99 7625.84,6948.93 ; 7884.94,5582.99 7884.94,6948.93 ; 8260.1,5582.99 8260.1,6948.93 ; 8983.48,5582.99 8983.48,6948.93 ; 6319.42,5582.99 9549.94,5582.99 9549.94,6948.93 6319.42,6948.93 6319.42,5582.99
  text "Symbol" at 6393.92,6862 h72
  text "Quantity" at 6694.53,6862 h72
  text "Finished Hole Size" at 7026.53,6862 h72
  text "Plated" at 7663.09,6862 h72
  text "Hole Type" at 7922.19,6862 h72
  text "Drill Layer Pair" at 8297.35,6862 h72
  text "Hole Tolerance" at 9020.73,6862 h72
  text "4" at 6694.53,6737.83 h60
  text "35.43mil (0.900mm)" at 7026.53,6737.83 h60
  text "NPTH" at 7663.09,6737.83 h60
  text "Round" at 7922.19,6737.83 h60
  text "Top Layer - Bottom Layer" at 8297.35,6737.83 h60
  text "4" at 6694.53,6613.65 h60
  text "133.86mil (3.400mm)" at 7026.53,6613.65 h60
  text "NPTH" at 7663.09,6613.65 h60
  text "Round" at 7922.19,6613.65 h60
  text "Top Layer - Bottom Layer" at 8297.35,6613.65 h60
  text "146" at 6694.53,6489.47 h60
  text "7.87mil (0.200mm)" at 7026.53,6489.47 h60
  text "PTH" at 7663.09,6489.47 h60
  text "Round" at 7922.19,6489.47 h60
  text "Top Layer - Bottom Layer" at 8297.35,6489.47 h60
  text "2578" at 6694.53,6365.3 h60
  text "12.01mil (0.305mm)" at 7026.53,6365.3 h60
  text "PTH" at 7663.09,6365.3 h60
  text "Round" at 7922.19,6365.3 h60
  text "Top Layer - Bottom Layer" at 8297.35,6365.3 h60
  text "33" at 6694.53,6241.12 h60
  text "40.00mil (1.016mm)" at 7026.53,6241.12 h60
  text "PTH" at 7663.09,6241.12 h60
  text "Round" at 7922.19,6241.12 h60
  text "Top Layer - Bottom Layer" at 8297.35,6241.12 h60
  text "2" at 6694.53,6116.95 h60
  text "40.16mil (1.020mm)" at 7026.53,6116.95 h60
  text "PTH" at 7663.09,6116.95 h60
  text "Round" at 7922.19,6116.95 h60
  text "Top Layer - Bottom Layer" at 8297.35,6116.95 h60
  text "8" at 6694.53,5992.77 h60
  text "42.91mil (1.090mm)" at 7026.53,5992.77 h60
  text "PTH" at 7663.09,5992.77 h60
  text "Round" at 7922.19,5992.77 h60
  text "Top Layer - Bottom Layer" at 8297.35,5992.77 h60
  text "20" at 6694.53,5868.59 h60
  text "49.21mil (1.250mm)" at 7026.53,5868.59 h60
  text "PTH" at 7663.09,5868.59 h60
  text "Round" at 7922.19,5868.59 h60
  text "Top Layer - Bottom Layer" at 8297.35,5868.59 h60
  text "4" at 6694.53,5744.42 h60
  text "125.98mil (3.200mm)" at 7026.53,5744.42 h60
  text "PTH" at 7663.09,5744.42 h60
  text "Round" at 7922.19,5744.42 h60
  text "Top Layer - Bottom Layer" at 8297.35,5744.42 h60
  text "2799 Total" at 6694.53,5620.24 h60
  text ".Layer_Name" at 577,-858.49 h60
M17 Embedded Cavity:
  text ".Layer_Name" at 577,-858.49 h60
M18 Embedded Assembly:
  text ".Layer_Name" at 577,-858.49 h60
M19 Embedded Keepout:
  text ".Layer_Name" at 577,-858.49 h60

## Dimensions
0,-400 to 1000,-400 on M2 Board Dimensions
0,0 to 0,4192.91 on M2 Board Dimensions
0,0 to 11269.69,-246.06 on M2 Board Dimensions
